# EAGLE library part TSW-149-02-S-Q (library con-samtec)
THROUGH-HOLE .025" SQ POST HEADER Source: Samtec TSW.pdf
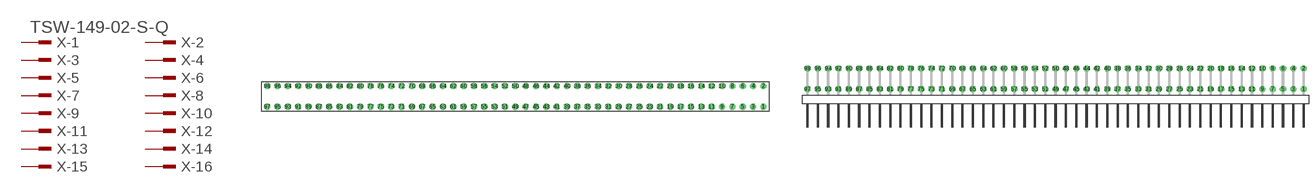
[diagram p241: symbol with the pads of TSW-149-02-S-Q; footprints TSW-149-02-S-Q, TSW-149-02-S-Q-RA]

Designator prefix X; gates -1=MPINV -2=MPIN -3=MPIN -4=MPIN -5=MPIN -6=MPIN -7=MPIN -8=MPIN -9=MPIN -10=MPIN -11=MPIN -12=MPIN -13=MPIN -14=MPIN -15=MPIN -16=MPIN -17=MPIN -18=MPIN -19=MPIN -20=MPIN -21=MPIN -22=MPIN -23=MPIN -24=MPIN -25=MPIN -26=MPIN -27=MPIN -28=MPIN -29=MPIN -30=MPIN -31=MPIN -32=MPIN -33=MPIN -34=MPIN -35=MPIN -36=MPIN -37=MPIN -38=MPIN -39=MPIN -40=MPIN -41=MPIN -42=MPIN -43=MPIN -44=MPIN -45=MPIN -46=MPIN -47=MPIN -48=MPIN -49=MPIN -50=MPIN -51=MPIN -52=MPIN -53=MPIN -54=MPIN -55=MPIN -56=MPIN -57=MPIN -58=MPIN -59=MPIN -60=MPIN -61=MPIN -62=MPIN -63=MPIN -64=MPIN -65=MPIN -66=MPIN -67=MPIN -68=MPIN -69=MPIN -70=MPIN -71=MPIN -72=MPIN -73=MPIN -74=MPIN -75=MPIN -76=MPIN -77=MPIN -78=MPIN -79=MPIN -80=MPIN -81=MPIN -82=MPIN -83=MPIN -84=MPIN -85=MPIN -86=MPIN -87=MPIN -88=MPIN -89=MPIN -90=MPIN -91=MPIN -92=MPIN -93=MPIN -94=MPIN -95=MPIN -96=MPIN -97=MPIN -98=MPIN

## TSW-149-02-S-Q (OC_FARNELL: unknown; OC_NEWARK: unknown)  [TSW-149-02-S-Q]
1  -1:1  pas
2  -2:1  pas
3  -3:1  pas
4  -4:1  pas
5  -5:1  pas
6  -6:1  pas
7  -7:1  pas
8  -8:1  pas
9  -9:1  pas
10  -10:1  pas
11  -11:1  pas
12  -12:1  pas
13  -13:1  pas
14  -14:1  pas
15  -15:1  pas
16  -16:1  pas
17  -17:1  pas
18  -18:1  pas
19  -19:1  pas
20  -20:1  pas
21  -21:1  pas
22  -22:1  pas
23  -23:1  pas
24  -24:1  pas
25  -25:1  pas
26  -26:1  pas
27  -27:1  pas
28  -28:1  pas
29  -29:1  pas
30  -30:1  pas
31  -31:1  pas
32  -32:1  pas
33  -33:1  pas
34  -34:1  pas
35  -35:1  pas
36  -36:1  pas
37  -37:1  pas
38  -38:1  pas
39  -39:1  pas
40  -40:1  pas
41  -41:1  pas
42  -42:1  pas
43  -43:1  pas
44  -44:1  pas
45  -45:1  pas
46  -46:1  pas
47  -47:1  pas
48  -48:1  pas
49  -49:1  pas
50  -50:1  pas
51  -51:1  pas
52  -52:1  pas
53  -53:1  pas
54  -54:1  pas
55  -55:1  pas
56  -56:1  pas
57  -57:1  pas
58  -58:1  pas
59  -59:1  pas
60  -60:1  pas
61  -61:1  pas
62  -62:1  pas
63  -63:1  pas
64  -64:1  pas
65  -65:1  pas
66  -66:1  pas
67  -67:1  pas
68  -68:1  pas
69  -69:1  pas
70  -70:1  pas
71  -71:1  pas
72  -72:1  pas
73  -73:1  pas
74  -74:1  pas
75  -75:1  pas
76  -76:1  pas
77  -77:1  pas
78  -78:1  pas
79  -79:1  pas
80  -80:1  pas
81  -81:1  pas
82  -82:1  pas
83  -83:1  pas
84  -84:1  pas
85  -85:1  pas
86  -86:1  pas
87  -87:1  pas
88  -88:1  pas
89  -89:1  pas
90  -90:1  pas
91  -91:1  pas
92  -92:1  pas
93  -93:1  pas
94  -94:1  pas
95  -95:1  pas
96  -96:1  pas
97  -97:1  pas
98  -98:1  pas

## TSW-149-02-S-Q-RA (OC_FARNELL: unknown; OC_NEWARK: unknown)  [TSW-149-02-S-Q-RA]
Pads as for TSW-149-02-S-Q

## Footprint TSW-149-02-S-Q (pad centres in mm)
THROUGH-HOLE .025" SQ POST HEADER Source: Samtec TSW.pdf
drill 1 pad 1.5 octagon: 1 60.96,-2.54; 2 60.96,2.54; 3 58.42,-2.54; 4 58.42,2.54; 5 55.88,-2.54; 6 55.88,2.54; 7 53.34,-2.54; 8 53.34,2.54; 9 50.8,-2.54; 10 50.8,2.54; 11 48.26,-2.54; 12 48.26,2.54; 13 45.72,-2.54; 14 45.72,2.54; 15 43.18,-2.54; 16 43.18,2.54; 17 40.64,-2.54; 18 40.64,2.54; 19 38.1,-2.54; 20 38.1,2.54; 21 35.56,-2.54; 22 35.56,2.54; 23 33.02,-2.54; 24 33.02,2.54; 25 30.48,-2.54; 26 30.48,2.54; 27 27.94,-2.54; 28 27.94,2.54; 29 25.4,-2.54; 30 25.4,2.54; 31 22.86,-2.54; 32 22.86,2.54; 33 20.32,-2.54; 34 20.32,2.54; 35 17.78,-2.54; 36 17.78,2.54; 37 15.24,-2.54; 38 15.24,2.54; 39 12.7,-2.54; 40 12.7,2.54; 41 10.16,-2.54; 42 10.16,2.54; 43 7.62,-2.54; 44 7.62,2.54; 45 5.08,-2.54; 46 5.08,2.54; 47 2.54,-2.54; 48 2.54,2.54; 49 0,-2.54; 50 0,2.54; 51 -2.54,-2.54; 52 -2.54,2.54; 53 -5.08,-2.54; 54 -5.08,2.54; 55 -7.62,-2.54; 56 -7.62,2.54; 57 -10.16,-2.54; 58 -10.16,2.54; 59 -12.7,-2.54; 60 -12.7,2.54; 61 -15.24,-2.54; 62 -15.24,2.54; 63 -17.78,-2.54; 64 -17.78,2.54; 65 -20.32,-2.54; 66 -20.32,2.54; 67 -22.86,-2.54; 68 -22.86,2.54; 69 -25.4,-2.54; 70 -25.4,2.54; 71 -27.94,-2.54; 72 -27.94,2.54; 73 -30.48,-2.54; 74 -30.48,2.54; 75 -33.02,-2.54; 76 -33.02,2.54; 77 -35.56,-2.54; 78 -35.56,2.54; 79 -38.1,-2.54; 80 -38.1,2.54; 81 -40.64,-2.54; 82 -40.64,2.54; 83 -43.18,-2.54; 84 -43.18,2.54; 85 -45.72,-2.54; 86 -45.72,2.54; 87 -48.26,-2.54; 88 -48.26,2.54; 89 -50.8,-2.54; 90 -50.8,2.54; 91 -53.34,-2.54; 92 -53.34,2.54; 93 -55.88,-2.54; 94 -55.88,2.54; 95 -58.42,-2.54; 96 -58.42,2.54; 97 -60.96,-2.54; 98 -60.96,2.54

## Footprint TSW-149-02-S-Q-RA (pad centres in mm)
THROUGH-HOLE .025" SQ POST HEADER Source: Samtec TSW.pdf
drill 1 pad 1.5 octagon: 1 60.96,1.524; 2 60.96,6.604; 3 58.42,1.524; 4 58.42,6.604; 5 55.88,1.524; 6 55.88,6.604; 7 53.34,1.524; 8 53.34,6.604; 9 50.8,1.524; 10 50.8,6.604; 11 48.26,1.524; 12 48.26,6.604; 13 45.72,1.524; 14 45.72,6.604; 15 43.18,1.524; 16 43.18,6.604; 17 40.64,1.524; 18 40.64,6.604; 19 38.1,1.524; 20 38.1,6.604; 21 35.56,1.524; 22 35.56,6.604; 23 33.02,1.524; 24 33.02,6.604; 25 30.48,1.524; 26 30.48,6.604; 27 27.94,1.524; 28 27.94,6.604; 29 25.4,1.524; 30 25.4,6.604; 31 22.86,1.524; 32 22.86,6.604; 33 20.32,1.524; 34 20.32,6.604; 35 17.78,1.524; 36 17.78,6.604; 37 15.24,1.524; 38 15.24,6.604; 39 12.7,1.524; 40 12.7,6.604; 41 10.16,1.524; 42 10.16,6.604; 43 7.62,1.524; 44 7.62,6.604; 45 5.08,1.524; 46 5.08,6.604; 47 2.54,1.524; 48 2.54,6.604; 49 0,1.524; 50 0,6.604; 51 -2.54,1.524; 52 -2.54,6.604; 53 -5.08,1.524; 54 -5.08,6.604; 55 -7.62,1.524; 56 -7.62,6.604; 57 -10.16,1.524; 58 -10.16,6.604; 59 -12.7,1.524; 60 -12.7,6.604; 61 -15.24,1.524; 62 -15.24,6.604; 63 -17.78,1.524; 64 -17.78,6.604; 65 -20.32,1.524; 66 -20.32,6.604; 67 -22.86,1.524; 68 -22.86,6.604; 69 -25.4,1.524; 70 -25.4,6.604; 71 -27.94,1.524; 72 -27.94,6.604; 73 -30.48,1.524; 74 -30.48,6.604; 75 -33.02,1.524; 76 -33.02,6.604; 77 -35.56,1.524; 78 -35.56,6.604; 79 -38.1,1.524; 80 -38.1,6.604; 81 -40.64,1.524; 82 -40.64,6.604; 83 -43.18,1.524; 84 -43.18,6.604; 85 -45.72,1.524; 86 -45.72,6.604; 87 -48.26,1.524; 88 -48.26,6.604; 89 -50.8,1.524; 90 -50.8,6.604; 91 -53.34,1.524; 92 -53.34,6.604; 93 -55.88,1.524; 94 -55.88,6.604; 95 -58.42,1.524; 96 -58.42,6.604; 97 -60.96,1.524; 98 -60.96,6.604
